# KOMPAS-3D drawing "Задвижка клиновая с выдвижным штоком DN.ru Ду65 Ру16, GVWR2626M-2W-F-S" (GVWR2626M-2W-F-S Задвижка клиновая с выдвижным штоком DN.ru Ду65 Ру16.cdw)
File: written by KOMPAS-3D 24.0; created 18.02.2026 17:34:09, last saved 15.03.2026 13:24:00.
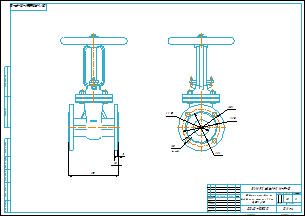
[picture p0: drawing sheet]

Document properties: Автор: R2D2; Форматы листов документа: A2; Полное имя файла: GVWR2626M-2W-F-S Задвижка клиновая с выдвижным штоком DN.ru Ду65 Ру16.m3d; Масса: 18; Наименование: Задвижка клиновая с выдвижным штоком DN.ru Ду65 Ру16; Количество листов документа: 1; Примечание: D040-10500

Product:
- Component [detail]: Деталь2  | qty 1  | pos. 1  | Автор: R2D2; additional columns: Типовые; source file: исходные материалы\Деталь2 Деталь2.m3d
- Component [detail]: AS 1110 - M12 x 45  | qty 4  | pos. 2  | Комментарий: Болты и винты   шестигранные точные   метрические ISO; Автор: R2D2; additional columns: Сталь, мягкая; source file: исходные материалы\AS 1110 - M12 x 45 AS 1110 - M12 x 45.m3d
- Component [detail]: ANSI B18.2.4.2M - M12x1,75 - 18  | designation ANSI B18.2.4.2M - M12x1,75  | qty 4  | pos. 3  | Комментарий: Типы метрических   шестигранных гаек   2; Автор: R2D2; additional columns: Сталь, мягкая; source file: исходные материалы\ANSI B18.2.4.2M - M12x1,75 ANSI B18.2.4.2M - M12x1,75 - 18.m3d
- Component [detail]: ANSI B18.2.4.2M - M5x0,8 - 8  | designation ANSI B18.2.4.2M - M5x0,8  | qty 1  | pos. 4  | Комментарий: Типы метрических   шестигранных гаек   2; Автор: R2D2; additional columns: Сталь, мягкая; source file: исходные материалы\ANSI B18.2.4.2M - M5x0,8 ANSI B18.2.4.2M - M5x0,8 - 8.m3d
- Component [detail]: Деталь1  | qty 1  | pos. 5  | Автор: R2D2; additional columns: Типовые; source file: исходные материалы\2.m3d
- Component [detail]: Фланец  | qty 1  | pos. 5  | Автор: R2D2; additional columns: Типовые; source file: исходные материалы\Фланец DN65 PN16 b18.m3d
- Component [detail]: Фланец  | designation 01  | qty 1  | pos. 6  | Автор: R2D2; additional columns: Типовые; source file: исходные материалы\Фланец DN65 PN16 b18.m3d
- Component [detail]: ANSI B18.2.4.2M - M5x0,8 - 8  | designation ANSI B18.2.4.2M - M5x0,8-01  | qty 1  | pos. 7  | Комментарий: Типы метрических   шестигранных гаек   2; Автор: R2D2; additional columns: Сталь, мягкая; source file: исходные материалы\ANSI B18.2.4.2M - M5x0,8 ANSI B18.2.4.2M - M5x0,8 - 8.m3d
- Component [detail]: Деталь1  | qty 1  | Автор: R2D2; additional columns: Типовые; source file: исходные материалы\3.m3d
- Part/product: Задвижка клиновая с выдвижным штоком DN.ru Ду65 Ру16  | designation GVWR2626M-2W-F-S
    Масса: 18
    Раздел спецификации: Прочие изделия
    Примечание: D040-10500

Views: Вид 1, Спереди
Referenced files in E:\Работа\Зайцев\GVWR2626M-2W-F-S Задвижка клиновая с выдвижным штоком DN.ru Ду50-300 Ру16\DN50\: GVWR2626M-2W-F-S Задвижка клиновая с выдвижным штоком DN.ru Ду50 Ру16.m3d
Referenced files in E:\Работа\Зайцев\GVWR2626M-2W-F-S Задвижка клиновая с выдвижным штоком DN.ru Ду50-300 Ру16\DN65\: GVWR2626M-2W-F-S Задвижка клиновая с выдвижным штоком DN.ru Ду65 Ру16.m3d
Referenced files in E:\Работа\Зайцев\Для компаса\: чертеж DN.ru А3.cdt
Referenced files in E:\Работа\Зайцев\GVWR2626M-2W-F-S Задвижка клиновая с выдвижным штоком DN.ru Ду50-300 Ру16\DN65\исходные материалы\: Деталь2 Деталь2.m3d, AS 1110 - M12 x 45 AS 1110 - M12 x 45.m3d, ANSI B18.2.4.2M - M12x1,75 ANSI B18.2.4.2M - M12x1,75 - 18.m3d, ANSI B18.2.4.2M - M5x0,8 ANSI B18.2.4.2M - M5x0,8 - 8.m3d, 2.m3d, Фланец DN65 PN16 b18.m3d, 3.m3d
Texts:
  GVWR2626M-2W-F-S
  чертеж DN.ru А3.cdt
  Задвижка клиновая с
  выдвижным штоком DN.ru
  Ду65 Ру16
  Твердое тело1
  Деталь2
  Деталь2 Деталь2
  Solid1
  AS 1110 - M12 x 45
  AS 1110 - M12 x 45 AS 1110 - M12 x 45
  ANSI B18.2.4.2M - M12x1,75 - 18
  ANSI B18.2.4.2M - M12x1,75
  ANSI B18.2.4.2M - M12x1,75 ANSI B18.2.4.2M - M12x1,75 - 18
  ANSI B18.2.4.2M - M5x0,8 - 8
  ANSI B18.2.4.2M - M5x0,8
  ANSI B18.2.4.2M - M5x0,8 ANSI B18.2.4.2M - M5x0,8 - 8
  Деталь1
  Деталь1 Деталь1
  Фланец
  ANSI B18.2.4.2M - M5x0,8-01 ANSI B18.2.4.2M - M5x0,8 - 8
  Задвижка клиновая с выдвижным штоком DN.ru Ду65 Ру16
  GVWR2626M-2W-F-S Задвижка клиновая с выдвижным штоком DN.ru Ду65 Ру16
Dimensions and other numbers on the sheet: 0; 3; 2; 4; 195; 18; 1:2; 1; 01; -01 Фланец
